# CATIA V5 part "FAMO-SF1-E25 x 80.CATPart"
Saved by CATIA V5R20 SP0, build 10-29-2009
Part number: FAMO-SF1-E25 x 80
Definition: NONE
Nomenclature: FAMO-SF1-E25 x 80
Source: Unknown
Description: FAMO-SF1-E25 x 80
Bounding box of the stored display mesh (mm): x -57 to 23, y -22 to 22, z -22 to 22
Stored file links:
  C:\Users\Utente\Desktop\IO LAVORO\3D X SITO CF\X SITO\FAMO\FAMO-SF1-E25 x 80.CATPart
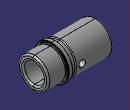
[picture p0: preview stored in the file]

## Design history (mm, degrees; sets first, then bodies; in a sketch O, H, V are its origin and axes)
Body1 "FAMO-SF1-E25 x 80" (main body)
  Solid1: solid without history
